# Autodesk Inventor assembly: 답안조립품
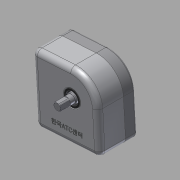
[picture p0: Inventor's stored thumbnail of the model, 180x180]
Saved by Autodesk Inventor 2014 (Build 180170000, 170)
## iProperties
Created: 2015-10
Part Number: 답안조립품
Document SubType Name: Assembly
Designer: youjin04
Author: youjin04
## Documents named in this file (13)
- C:\Users\youjin04\Desktop\451019V1004\답안조립품.iam
- C:\Users\youjin04\Desktop\451019V1004\본체.ipt
- C:\Users\youjin04\Desktop\451019V1004\앞커버.ipt
- C:\Users\youjin04\Desktop\451019V1004\M4 x 0.7.ipt
- C:\Users\youjin04\Desktop\451019V1004\오일실 12 x 22.ipt
- C:\Users\youjin04\Desktop\451019V1004\축 커버.ipt
- C:\Users\youjin04\Desktop\451019V1004\M3 x 0.5.ipt
- C:\Users\youjin04\Desktop\451019V1004\오일실 15 x 25.ipt
- C:\Users\youjin04\Desktop\451019V1004\베어링 6002.ipt
- C:\Users\youjin04\Desktop\451019V1004\로드 축.ipt
- C:\Users\youjin04\Desktop\451019V1004\로드.ipt
- C:\Users\youjin04\Desktop\451019V1004\편심 축.ipt
- C:\Users\youjin04\Desktop\451019V1004\베어링 6001.ipt
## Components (9 placed, 2 different names)
1. M4 x 0.7:1
2. M4 x 0.7:2
3. M4 x 0.7:3
4. M4 x 0.7:4
5. M4 x 0.7:5
6. M3 x 0.5:1
7. M3 x 0.5:2
8. M3 x 0.5:3
9. M3 x 0.5:4
